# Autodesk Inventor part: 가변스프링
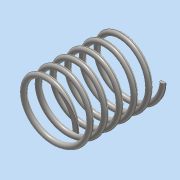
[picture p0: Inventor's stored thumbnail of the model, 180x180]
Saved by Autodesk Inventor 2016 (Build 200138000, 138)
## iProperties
Created: 2018-11
Part Number: 가변스프링
Material: 스테인레스 스틸
Document SubType Name: Modeling
Designer: 공506_41
Density: 8 g/cm^3
Appearance: 반연마
Mass: 84.1963 g
Surface Area: 106.449 cm^2
Volume: 10.5245 cm^3
Author: 공506_41
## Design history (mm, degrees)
sketch "스케치1"
  geometry: L1 (0, 0)-(22.5, 0); L2 (22.5, 0)-(22.5, 67.25); L3 (22.5, 67.25)-(0, 67.25); L4 (0, 67.25)-(0, 0); C1 r 2 at (22.5, 0)
  constraints: 8 end point, 2 parallel, 1 centre point, 1 coincident, 1 horizontal, 1 perpendicular
  dimensions: "d1" = 67.25 distance of L3.end L1.start (derived); "d2" = 4 diameter of C1; "d3" = 45 diameter of L2 L4
feature "코일1" sketch "스케치1" pitch "d4" = 10; turns "d6" = 6; dims "d5" = 67.25 (= d1), "d7" = 0, angle "d8" = 90 deg, angle "d9" = 90 deg, "d10" = 0, "d11" = 0
sketch "스케치2"
  geometry: L1 (67.25, 50)-(0, 50); L2 (0, 50)-(0, -50); L3 (0, -50)-(67.25, -50); L4 (67.25, -50)-(67.25, 50); 2 further points
  constraints: 8 end point, 2 parallel, 1 coincident, 1 horizontal, 1 midpoint, 1 perpendicular
  dimensions: "d12" = 67.25 distance of L1.start L1.end (= d1); "d13" = 100 distance of L3.end L1.start
extrude "돌출1" sketch "스케치2" stored distance "d14" = 50; taper "d15" = 0 deg
node "솔리드1"
